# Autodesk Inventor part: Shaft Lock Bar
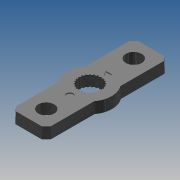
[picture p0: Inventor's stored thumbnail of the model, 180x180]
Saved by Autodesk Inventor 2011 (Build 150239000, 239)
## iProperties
Created: 2010-06
Part Number: Shaft Lock Bar
Document SubType Name: Modeling
Designer: Phil
Density: 1 g/cm^3
Author: Phil
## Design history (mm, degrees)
sketch "Sketch1"
  geometry: L1 (12.696, 10.049)-(0, 10.049); L2 (0, 10.049)-(-1.238, 8.812); L3 (-1.238, 8.812)-(-1.238, 1.238); L4 (-1.238, 1.238)-(0, 0); L5 (0, 0)-(12.696, 0); L6 (20.279, 0)-(32.974, 0); L7 (32.974, 0)-(34.212, 1.238); L8 (34.212, 1.238)-(34.212, 8.812); L9 (34.212, 8.812)-(32.974, 10.049); L10 (32.974, 10.049)-(20.279, 10.049); L11 (21.973, 4.148)-(20.449, 5.025); L12 (20.449, 5.025)-(21.973, 5.901); L13 (21.973, 5.901)-(21.973, 4.148); C1 r 1 at (10.598, 5.025); C2 r 2.311 at (3.787, 5.025); C3 r 2.311 at (29.187, 5.025); A1 r 3.106 centre (16.487, 5.025) between (17.501, 2.088) and (17.846, 2.231); A2 r 0.224 centre (18.057, 2.305) between (17.846, 2.231) and (18.227, 2.451); A3 r 3.106 centre (16.487, 5.025) between (18.227, 2.451) and (18.523, 2.678); A4 r 0.224 centre (18.707, 2.804) between (18.523, 2.678) and (18.834, 2.989); A5 r 3.106 centre (16.487, 5.025) between (18.834, 2.989) and (19.061, 3.285); A6 r 0.224 centre (19.206, 3.455) between (19.061, 3.285) and (19.28, 3.666); A7 r 0.224 centre (19.52, 4.212) between (19.423, 4.01) and (19.537, 4.435); A8 r 0.224 centre (17.3, 1.992) between (17.077, 1.975) and (17.501, 2.088); A9 r 3.106 centre (16.487, 5.025) between (16.707, 1.926) and (17.077, 1.975); A10 r 6.295 centre (16.487, 5.025) between (12.696, 0) and (20.279, 0); A11 r 0.224 centre (16.487, 1.885) between (16.267, 1.926) and (16.707, 1.926); A12 r 3.106 centre (16.487, 5.025) between (13.693, 6.383) and (13.551, 6.039); A13 r 0.224 centre (13.77, 6.593) between (13.914, 6.765) and (13.693, 6.383); A14 r 3.106 centre (16.487, 5.025) between (13.437, 5.614) and (13.388, 5.245); A15 r 0.224 centre (13.457, 5.836) between (13.551, 6.039) and (13.437, 5.614); A16 r 3.106 centre (16.487, 5.025) between (19.28, 3.666) and (19.423, 4.01); A17 r 6.295 centre (16.487, 5.025) between (20.279, 10.049) and (12.696, 10.049); A18 r 3.106 centre (16.487, 5.025) between (15.472, 7.961) and (15.128, 7.818); A19 r 0.224 centre (15.675, 8.055) between (15.898, 8.075) and (15.472, 7.961); A20 r 3.106 centre (16.487, 5.025) between (14.14, 7.06) and (13.914, 6.765); A21 r 0.224 centre (14.269, 7.243) between (14.452, 7.371) and (14.14, 7.06); A22 r 3.106 centre (16.487, 5.025) between (14.747, 7.598) and (14.452, 7.371); A23 r 0.224 centre (14.919, 7.741) between (15.128, 7.818) and (14.747, 7.598); A24 r 3.106 centre (16.487, 5.025) between (15.897, 1.975) and (16.267, 1.926); A25 r 0.224 centre (15.674, 1.992) between (15.473, 2.088) and (15.897, 1.975); A26 r 3.106 centre (16.487, 5.025) between (15.128, 2.231) and (15.473, 2.088); A27 r 3.106 centre (16.487, 5.025) between (14.451, 2.678) and (14.747, 2.451); A28 r 0.224 centre (14.267, 2.804) between (14.141, 2.989) and (14.451, 2.678); A29 r 3.106 centre (16.487, 5.025) between (13.913, 3.285) and (14.141, 2.989); A30 r 3.106 centre (16.487, 5.025) between (13.551, 4.01) and (13.694, 3.666); A31 r 3.106 centre (16.487, 5.025) between (13.388, 4.804) and (13.437, 4.435); A32 r 0.224 centre (13.454, 4.212) between (13.437, 4.435) and (13.551, 4.01); A33 r 0.224 centre (13.768, 3.455) between (13.694, 3.666) and (13.913, 3.285); A34 r 0.224 centre (14.917, 2.305) between (14.747, 2.451) and (15.128, 2.231); A35 r 0.224 centre (13.35, 5.025) between (13.388, 5.245) and (13.388, 4.804); A36 r 3.106 centre (16.487, 5.025) between (16.267, 8.123) and (15.898, 8.075); A37 r 0.224 centre (16.487, 8.165) between (16.707, 8.123) and (16.267, 8.123); A38 r 3.106 centre (16.487, 5.025) between (17.077, 8.075) and (16.707, 8.123); A39 r 0.224 centre (17.3, 8.058) between (17.501, 7.961) and (17.077, 8.075); A40 r 0.224 centre (19.627, 5.025) between (19.586, 4.805) and (19.586, 5.244); A41 r 3.106 centre (16.487, 5.025) between (19.586, 5.244) and (19.537, 5.614); A42 r 0.224 centre (19.52, 5.837) between (19.537, 5.614) and (19.423, 6.039); A43 r 3.106 centre (16.487, 5.025) between (19.423, 6.039) and (19.28, 6.384); A44 r 0.224 centre (19.206, 6.595) between (19.28, 6.384) and (19.061, 6.764); A45 r 3.106 centre (16.487, 5.025) between (19.061, 6.764) and (18.834, 7.06); A46 r 0.224 centre (18.707, 7.245) between (18.834, 7.06) and (18.523, 7.371); A47 r 3.106 centre (16.487, 5.025) between (18.523, 7.371) and (18.227, 7.598); A48 r 0.224 centre (18.057, 7.744) between (18.227, 7.598) and (17.846, 7.818); A49 r 3.106 centre (16.487, 5.025) between (17.846, 7.818) and (17.501, 7.961); A50 r 3.106 centre (16.487, 5.025) between (19.537, 4.435) and (19.586, 4.805); 1 further point
  constraints: 100 point on circle, 53 centre point, 26 end point
extrude "Extrusion1" new body sketch "Sketch1" distance "d0" = 3.175; taper "d1" = 2 deg
hole "Hole1" sketch "Sketch1" diameter "d2" = 4.6228; stored, may be unused: countersink angle "d6" = 82 deg, drill point angle "d8" = 118 deg; dims "d3" = 19.05, "d4" = 9.525, "d5" = 6.35, "d7" = 25.4
extrude "Extrusion2" cut sketch "Sketch1" distance "d9" = 0.254; taper "d10" = 0 deg
extrude "Extrusion3" cut sketch "Sketch1" stored distance "d11" = 0; taper "d12" = 2 deg
sketch "Sketch2"
  geometry: L1 (32.376, 9.105)-(30.187, 9.105); L2 (7.473, 5.495)-(10.3, 5.495); L3 (10.3, 4.554)-(7.473, 4.554); L4 (11.747, 9.105)-(4.787, 9.105); L5 (-0.023, 10.105)-(12.677, 10.105); L6 (4.787, 0.945)-(11.747, 0.945); L7 (12.677, -0.055)-(-0.023, -0.055); L8 (-0.293, 4.025)-(-0.293, 1.836); L9 (-1.293, 1.215)-(-1.293, 8.835); L10 (0.245, 1.091)-(-0.147, 1.482); L11 (0.598, 0.945)-(2.787, 0.945); L12 (33.267, 6.025)-(33.267, 8.213); L13 (34.267, 8.835)-(34.267, 1.215); L14 (-0.023, -0.055)-(-1.293, 1.215); L15 (34.267, 1.215)-(32.997, -0.055); L16 (33.267, 1.836)-(33.267, 4.025); L17 (33.121, 1.482)-(32.729, 1.091); L18 (30.187, 0.945)-(32.376, 0.945); L19 (32.997, 10.105)-(34.267, 8.835); L20 (32.729, 8.958)-(33.121, 8.567); L21 (32.997, -0.055)-(20.297, -0.055); L22 (20.297, 10.105)-(32.997, 10.105); L23 (21.227, 0.945)-(28.187, 0.945); L24 (28.187, 9.105)-(21.227, 9.105); L25 (25.501, 4.554)-(22.674, 4.554); L26 (22.674, 5.495)-(25.501, 5.495); L27 (-1.293, 8.835)-(-0.023, 10.105); L28 (2.787, 9.105)-(0.598, 9.105); L29 (-0.293, 8.213)-(-0.293, 6.025); L30 (-0.147, 8.567)-(0.245, 8.958); C1 r 2.367 at (29.187, 5.025); C2 r 2.367 at (3.787, 5.025); C3 r 4.763 at (16.487, 5.025); A1 r 3.311 centre (29.187, 5.025) between (32.382, 5.893) and (30.056, 8.22); A2 r 3.311 centre (3.787, 5.025) between (6.989, 5.868) and (4.656, 8.22); A3 r 3.311 centre (3.787, 5.025) between (4.656, 1.829) and (6.989, 4.181); A4 r 0.5 centre (0.207, 1.836) between (-0.293, 1.836) and (-0.147, 1.482); A5 r 3.311 centre (3.787, 5.025) between (0.592, 4.156) and (2.918, 1.829); A6 r 0.5 centre (32.376, 8.605) between (32.729, 8.958) and (32.376, 9.105); A7 r 0.5 centre (32.767, 8.213) between (33.267, 8.213) and (33.121, 8.567); A8 r 0.5 centre (0.598, 1.445) between (0.245, 1.091) and (0.598, 0.945); A9 r 0.5 centre (32.767, 1.836) between (33.121, 1.482) and (33.267, 1.836); A10 r 3.311 centre (29.187, 5.025) between (30.056, 1.829) and (32.382, 4.156); A11 r 0.5 centre (32.376, 1.445) between (32.376, 0.945) and (32.729, 1.091); A12 r 3.311 centre (29.187, 5.025) between (28.318, 8.22) and (25.985, 5.868); A13 r 3.311 centre (29.187, 5.025) between (25.985, 4.181) and (28.318, 1.829); A14 r 6.35 centre (16.487, 5.025) between (12.677, -0.055) and (20.297, -0.055); A15 r 6.35 centre (16.487, 5.025) between (20.297, 10.105) and (12.677, 10.105); A16 r 0.3 centre (11.747, 8.805) between (11.982, 8.618) and (11.747, 9.105); A17 r 5.763 centre (16.487, 5.025) between (11.982, 8.618) and (10.794, 5.918); A18 r 5.763 centre (16.487, 5.025) between (20.992, 1.432) and (22.18, 4.131); A19 r 0.3 centre (21.227, 1.245) between (20.992, 1.432) and (21.227, 0.945); A20 r 5.763 centre (16.487, 5.025) between (22.18, 5.918) and (20.992, 8.618); A21 r 0.3 centre (21.227, 8.805) between (21.227, 9.105) and (20.992, 8.618); A22 r 0.3 centre (11.747, 1.245) between (11.747, 0.945) and (11.982, 1.432); A23 r 5.763 centre (16.487, 5.025) between (10.794, 4.131) and (11.982, 1.432); A24 r 3.311 centre (3.787, 5.025) between (2.918, 8.22) and (0.592, 5.893); A25 r 0.5 centre (0.207, 8.213) between (-0.147, 8.567) and (-0.293, 8.213); A26 r 0.5 centre (0.598, 8.605) between (0.598, 9.105) and (0.245, 8.958); 25 further points; 12 other entities
  constraints: 60 end point, 52 point on circle, 29 centre point, 88 other
extrude "Extrusion4" cut sketch "Sketch2" distance "d13" = 1.6764; taper "d14" = 0 deg
body "Solid1"
